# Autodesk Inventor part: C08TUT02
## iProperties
Created: 2009-04
Part Number: C08TUT02
Document SubType Name: Modeling
Designer: Sham
Density: 1 g/cm^3
Author: Sham
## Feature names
1. Extrusion1
2. Extrusion2
3. Extrusion3
4. Chamfer1
